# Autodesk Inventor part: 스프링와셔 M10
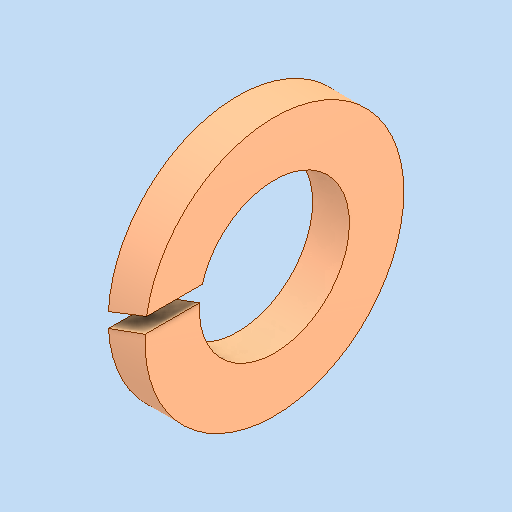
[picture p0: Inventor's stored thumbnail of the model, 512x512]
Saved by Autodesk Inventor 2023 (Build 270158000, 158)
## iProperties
Created: 2024-09
Part Number: 스프링와셔 M10
Material: 강철, 연강
Description: 스프링 잠금 와셔
Document SubType Name: Modeling
Designer: asung
Density: 7.85 g/cm^3
Appearance: 기본값
Author: jhkim
Sending System: Autodesk Inventor 2025
Preprocessor: ST-DEVELOPER v20
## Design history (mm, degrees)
feature "Solid1"
node "솔리드1"
